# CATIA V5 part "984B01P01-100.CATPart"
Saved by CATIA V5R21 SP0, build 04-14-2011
Part number: 984B01P01-115
Bounding box of the stored display mesh (mm): x -33.4 to 33.4, y -100 to 100, z -8 to 107
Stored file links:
  C:\Users\ALI OZGUN\Desktop\alhan\984B01P01-115.CATPart
  C:\Users\ALI OZGUN\Desktop\alhan\943B01P01.CATPart
  C:\Users\ALI OZGUN\Desktop\alhan\950B01P01.CATPart
  C:\Users\ALI OZGUN\Desktop\alhan\Product1.CATProduct
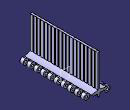
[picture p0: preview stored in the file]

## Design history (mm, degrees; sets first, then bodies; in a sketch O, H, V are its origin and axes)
Body1 (main body)
Body2
  Sketch1 on zx-plane, origin (0, 0, 0), H (-1, 0, 0), V (0, 0, 1)
    construction line L1 (25.4, 8) -> (25.4, -8)
    line L2 (25.4, -8) -> (-25.4, -8)
    construction line L3 (-25.4, -8) -> (-25.4, 8)
    line L4 (-25.4, 8) -> (25.4, 8)
    point P3 (-25.4, -8)
    arc A1 centre (25.4, 0) radius 8 from (25.4, 8) to (25.4, -8) cw
    arc A2 centre (-25.4, 0) radius 8 from (-25.4, 8) to (-25.4, -8) ccw
    point P7 (-25.4, -8)
    length L4 = 50.8
    length L3 = 16
    vertical: L1 V, L3 V
    horizontal: L2 H, L4 H
    equidistance: L1 L3 O, L2 L4 O
    tangency: A1 L2, A2 L4, A2 L2, L4 A1
    coincidence: P7 L2, P3 P7
  Pad1: profile Sketch1, direction (0, 1, 0), length 100, mirrored extent
  Sketch2 on zx-plane, origin (0, 0, 0), H (-1, 0, 0), V (0, 0, 1)
    circle A1 centre (25.4, 0) radius 3.15
    circle A2 centre (-25.4, 0) radius 3.15
  Pocket1: profile Sketch2, direction (0, -1, 0), length 204, mirrored extent
  Body3 "aramesefa"
    Sketch3 on face of Pad1 from Sketch1.L4, origin (0, 0, 8), H (1, 0, 0), V (0, 1, 0)
      line L1 (21.5, -80) -> (55.8232, -80)
      line L2 (55.8232, -80) -> (55.8232, -90.5)
      line L3 (55.8232, -90.5) -> (21.5, -90.5)
      line L4 (21.5, -90.5) -> (21.5, -80)
      reference projected line E1 (-25.4, -100) -> (25.4, -100) from edge [start face of Pad1 | face of Pad1 from Sketch1.L4]
      line L5 (-54.1233, -90) -> (-21.5, -90)
      line L6 (-21.5, -90) -> (-21.5, -100.5)
      line L7 (-21.5, -100.5) -> (-54.1233, -100.5)
      line L8 (-54.1233, -100.5) -> (-54.1233, -90)
      reference projected line E2 (-25.4, -100) -> (25.4, -100) from edge [start face of Pad1 | face of Pad1 from Sketch1.L4]
      distance L1 L3 = 10.5
      distance L3 E1 = 9.5
      distance L4 V = 21.5
      distance L5 L3 = 0.5
      distance L7 E2 = 0.5
      distance L6 L4 = 43
      horizontal: L1 H, L3 H, L5 H, L7 H
      vertical: L2 V, L4 V, L6 V, L8 V
    Pad2: profile Sketch3, direction (0, 0, 1), length 20, mirrored extent
    RectPattern1: of the body so far, direction 1 instances 10, spacing 20, along yz-plane
  Remove1: tool Body3
  Body4 "ALTBOSLUK"
    Sketch4 on zx-plane, origin (0, 0, 0), H (-1, 0, 0), V (0, 0, 1)
      line L1 (48.9583, 0) -> (33.4, 0)
      arc A1 centre (25.4, 0) radius 8 from (17.4, 0) to (33.4, 0) ccw
      line L2 (17.4, 0) -> (17.4, 0.2)
      arc A2 centre (15.4, 0.2) radius 2 from (17.4, 0.2) to (15.4, 2.2) ccw
      line L3 (15.4, 2.2) -> (5.5215, 2.2)
      arc A3 centre (5.5215, 0.2) radius 2 from (5.5215, 2.2) to (3.5325, 0.4091) ccw
      line L4 (3.5325, 0.4091) -> (2.9836, -4.8136)
      arc A4 centre (0, -4.4996) radius 3 from (-2.9836, -4.8136) to (2.9836, -4.8136) ccw
      line L5 (-2.9836, -4.8136) -> (-3.5325, 0.4091)
      arc A5 centre (-5.5215, 0.2) radius 2 from (-3.5325, 0.4091) to (-5.5215, 2.2) ccw
      line L6 (-5.5215, 2.2) -> (-15.4, 2.2)
      arc A6 centre (-15.4, 0.2) radius 2 from (-15.4, 2.2) to (-17.4, 0.2) ccw
      line L7 (-17.4, 0.2) -> (-17.4, 0)
      arc A7 centre (-25.4, 0) radius 8 from (-33.4, 0) to (-17.4, 0) ccw
      line L8 (-33.4, 0) -> (-46.3888, 0)
      line L9 (-46.3888, 0) -> (-46.3888, -17.807)
      line L10 (-46.3888, -17.807) -> (48.9583, -17.807)
      line L11 (48.9583, -17.807) -> (48.9583, 0)
      vertical: L9 V, L11 V
      horizontal: L10 H
    Pad3: profile Sketch4, direction (0, 1, 0), length 215, mirrored extent
  Remove2: tool Body4
  Body5 "KALANTIBOSALTMA"
    Sketch5 on face of Pad1 from Sketch1.L4, origin (0, 0, 8), H (1, 0, 0), V (0, 1, 0)
      line L1 (10, -80) -> (55.8232, -80)
      line L2 (55.8232, -80) -> (55.8232, -90.5)
      line L3 (55.8232, -90.5) -> (10, -90.5)
      line L4 (10, -90.5) -> (10, -80)
      reference projected line E1 (-25.4, -100) -> (25.4, -100) from edge [start face of Pad1 | face of Pad1 from Sketch1.L4]
      line L5 (-54.1233, -90) -> (-10, -90)
      line L6 (-10, -90) -> (-10, -100.5)
      line L7 (-10, -100.5) -> (-54.1233, -100.5)
      line L8 (-54.1233, -100.5) -> (-54.1233, -90)
      reference projected line E2 (-25.4, -100) -> (25.4, -100) from edge [start face of Pad1 | face of Pad1 from Sketch1.L4]
      distance L1 L3 = 10.5
      distance L3 E1 = 9.5
      distance L4 V = 10
      distance L5 L3 = 0.5
      distance L7 E2 = 0.5
      distance L6 L4 = 20
      horizontal: L1 H, L3 H, L5 H, L7 H
      vertical: L2 V, L4 V, L6 V, L8 V
    Pad4: profile Sketch5, direction (0, 0, 1), length 20, mirrored extent
    RectPattern2: of the body so far, direction 1 instances 10, spacing 20, along yz-plane
    Sketch6 on zx-plane, origin (0, 0, 0), H (-1, 0, 0), V (0, 0, 1)
      line L1 (108.0577, 2.2) -> (-84.5523, 2.2)
      fix: L1
    Pocket2: profile Sketch6, direction (0, -1, 0), length 215, mirrored extent
  Remove3: tool Body5
  Body6 "aramesefa ACILARI"
    Sketch7 on face of Pad1 from Sketch1.L4, origin (0, 0, 8), H (1, 0, 0), V (0, 1, 0)
      line L1 (21.5, -80) -> (55.8232, -80)
      line L2 (55.8232, -80) -> (55.8232, -90.5)
      line L3 (55.8232, -90.5) -> (21.5, -90.5)
      line L4 (21.5, -90.5) -> (21.5, -80)
      reference projected line E1 (-25.4, -100) -> (25.4, -100) from edge [start face of Pad1 | face of Pad1 from Sketch1.L4]
      line L5 (-54.1233, -90) -> (-21.5, -90)
      line L6 (-21.5, -90) -> (-21.5, -100.5)
      line L7 (-21.5, -100.5) -> (-54.1233, -100.5)
      line L8 (-54.1233, -100.5) -> (-54.1233, -90)
      reference projected line E2 (-25.4, -100) -> (25.4, -100) from edge [start face of Pad1 | face of Pad1 from Sketch1.L4]
      distance L1 L3 = 10.5
      distance L3 E1 = 9.5
      distance L4 V = 21.5
      distance L5 L3 = 0.5
      distance L7 E2 = 0.5
      distance L6 L4 = 43
      horizontal: L1 H, L3 H, L5 H, L7 H
      vertical: L2 V, L4 V, L6 V, L8 V
    Pad5: profile Sketch7, direction (0, 0, 1), length 20, mirrored extent
    Sketch8 on zx-plane, origin (0, 0, 0), H (-1, 0, 0), V (0, 0, 1)
      line L1 (67.6223, 8) -> (-70.015, 8)
      fix: L1
    Pocket3: profile Sketch8, direction (0, -1, 0), length 215, mirrored extent
    Draft1: Angle 45, Neutral face of Pocket3 from Sketch8.L1, PullDir face of Pocket3 from Sketch8.L1, SupportToDraft face of Pad5 from Sketch7.L6
    Draft2: Angle 45, Neutral face of Pocket3 from Sketch8.L1, PullDir face of Pocket3 from Sketch8.L1, SupportToDraft face of Pad5 from Sketch7.L4
    RectPattern3: of the body so far, direction 1 instances 10, spacing 20, along yz-plane
  Remove4: tool Body6
  Sketch9 on zx-plane, origin (0, 0, 0), H (-1, 0, 0), V (0, 0, 1)
    line L1 (0, 72) -> (0, 6.9718)
    point P1 (0, 72)
    reference projected line E1 (-25.4, -8) -> (25.4, -8) from edge [face of Pad1 from Sketch1.L2 | end face of Pad1]
    distance P1 E1 = 80
    coincidence: P1 V
    vertical: L1 V
  Sketch10 on zx-plane, origin (0, 0, 0), H (-1, 0, 0), V (0, 0, 1)
    line L1 (0, 5) -> (0, 107)
    point P1 (0, 5)
    point P2 (0, 107)
    reference projected line E1 (25.4, 8) -> (-25.4, 8) from edge [face of Pad1 from Sketch1.L4 | end face of Pad1]
    distance P1 H = 5
    distance P2 E1 = 99
    coincidence: P1 V
    vertical: L1 V
  Pad6: profile Sketch10, direction (0, 1, 0), length 100, mirrored extent, thin wall 6
  Body7
    Pad7: profile Sketch12, direction (0, 0, -1), up to face of Pad1 from Sketch1.L4
    Fillet1: radius 1.5, on edge [face of Pad7 from Sketch12.L1 | face of Pad7 from Sketch12.L3]; edge [face of Pad7 from Sketch12.L3 | face of Pad7 from Sketch12.L2]; edge [face of Pad7 from Sketch12.L9 | face of Pad7 from Sketch12.L7]; edge [face of Pad7 from Sketch12.L8 | face of Pad7 from Sketch12.L9]
    RectPattern4: of the body so far, direction 1 instances 18, spacing 10.75, along yz-plane
  Remove5: tool Body7
  Sketch11 on face of Pad6, origin (0, -100, 0), H (1, 0, 0), V (0, 0, 1)
    projected line E1 (3, 8) -> (25.4, 8) from edge [face of Pad6 | face of Pad1]
    projected line E2 (2, 8) -> (21.5, 8) from edge [face of Pad6 | face of Pad1]
    point P1 (3, 8)
    point P2 (25.4, 8)
    projected line E3 (3, 8) -> (3, 107) from edge [face of Pad6 | face of Pad6]
    point P3 (3, 8)
    offset line E4 (2, 8) -> (2, 107) from edge [face of Pad6 | face of Pad6]
    offset line E5 (2, 8) -> (2, 12.7166) from edge [face of Pad6 | face of Pad6]
    point P5 (2, 8)
    point P6 (2, 107)
    point P7 (2, 8)
    reference projected point E6 (21.5, 8) from edge [face of Pad1 | face of Pad5 from Sketch7.L4]
    arc A1 centre (21.5, 50.6681) radius 42.6681 from (2, 12.7166) to (21.5, 8) ccw
    point P9 (21.5, 8)
    point P10 (2, 12.7166)
    point P11 (-3, 8)
    point P12 (-2, 8)
    point P13 (-25.4, 8)
    point P14 (-21.5, 8)
    point P15 (-3, 8)
    point P16 (-2, 8)
    point P17 (-2, 12.7166)
    point P18 (-2, 107)
    arc A2 centre (-21.5, 50.6681) radius 42.6681 from (-2, 12.7166) to (-21.5, 8) cw
    point P20 (-21.5, 8)
    construction line L1 (-3, 8) -> (-25.4, 8)
    line L2 (-2, 8) -> (-21.5, 8)
    construction line L3 (-2, 8) -> (-2, 107)
    line L4 (-2, 8) -> (-2, 12.7166)
    coincidence: E6 A1
    symmetry: P1 P11 V, P5 P12 V, P2 P13 V, P9 P14 V, E6 P20 V, P3 P15 V, P7 P16 V, P10 P17 V, E1 L1 V, P6 P18 V, E4 L3 V, A1 A2 V, E1 L2 V, E4 L4 V
  Pad8: profile Sketch11, direction (0, 1, 0), up to face of Pad6
  Sketch12 on face of Pad6, origin (0, 0, 107), H (1, 0, 0), V (0, 1, 0)
    point P1 (2.5, -90)
    line L1 (2.5, -90) -> (3, -90)
    line L2 (3, -92.5) -> (2.5, -92.5)
    line L3 (2.5, -92.5) -> (2.5, -90)
    point P2 (3.8393, -92.5)
    point P3 (2.5, -92.5)
    reference projected line E1 (3, -100) -> (3, 100) from edge [face of Pad6 | face of Pad6]
    reference projected line E2 (-3, -100) -> (3, -100) from edge [start face of Pad6 | face of Pad6]
    projected line E3 (3, -100) -> (3, 100) from edge [face of Pad6 | face of Pad6]
    projected line E4 (3, -94.2462) -> (3, -92.5) from edge [face of Pad6 | face of Pad6]
    projected line E5 (3, -90) -> (3, -88.3449) from edge [face of Pad6 | face of Pad6]
    point P4 (3, -100)
    point P5 (3, 100)
    line L4 (3, -88.3449) -> (6.2768, -88.3449)
    point P6 (6.2768, -88.3449)
    line L5 (6.2768, -88.3449) -> (6.2768, -94.2462)
    point P7 (6.2768, -94.2462)
    line L6 (6.2768, -94.2462) -> (3, -94.2462)
    point P8 (3, -94.2462)
    point P9 (3, -88.3449)
    point P10 (3, -92.5)
    point P11 (3, -90)
    point P12 (3, -92.5)
    point P13 (3, -90)
    point P14 (-2.5, -90)
    point P15 (-3.8393, -92.5)
    point P16 (-2.5, -92.5)
    point P17 (-3, -100)
    point P18 (-6.2768, -88.3449)
    point P19 (-6.2768, -94.2462)
    point P20 (-3, -94.2462)
    point P21 (-3, -88.3449)
    point P22 (-3, -92.5)
    point P23 (-3, -90)
    point P24 (-3, -92.5)
    point P25 (-3, -90)
    line L7 (-2.5, -90) -> (-3, -90)
    line L8 (-3, -92.5) -> (-2.5, -92.5)
    line L9 (-2.5, -92.5) -> (-2.5, -90)
    point P26 (-3, 100)
    line L10 (-3, -88.3449) -> (-6.2768, -88.3449)
    line L11 (-6.2768, -88.3449) -> (-6.2768, -94.2462)
    line L12 (-6.2768, -94.2462) -> (-3, -94.2462)
    construction line L13 (-3, -100) -> (-3, 100)
    line L14 (-3, -94.2462) -> (-3, -92.5)
    line L15 (-3, -90) -> (-3, -88.3449)
    distance L1 L2 = 2.5
    distance L3 E1 = 0.5
    distance P2 E2 = 7.5
    horizontal: L1 H, L2 H, L4 H, L6 H
    vertical: L3 V, L5 V
    coincidence: L2 P10, L1 P11, E3 P12, E3 P13
    symmetry: P1 P14 V, P2 P15 V, P3 P16 V, P4 P17 V, P6 P18 V, P7 P19 V, P8 P20 V, P9 P21 V, P10 P22 V, P11 P23 V, P12 P24 V, P13 P25 V, L1 L7 V, L2 L8 V, L3 L9 V, P5 P26 V, E3 L13 V, L4 L10 V, L5 L11 V, L6 L12 V, E3 L15 V, E3 L14 V
Body8
  Solid1: linked copy from another document
  Translate1: Direction yz-plane, Length 50.8, ToTransfor Solid1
